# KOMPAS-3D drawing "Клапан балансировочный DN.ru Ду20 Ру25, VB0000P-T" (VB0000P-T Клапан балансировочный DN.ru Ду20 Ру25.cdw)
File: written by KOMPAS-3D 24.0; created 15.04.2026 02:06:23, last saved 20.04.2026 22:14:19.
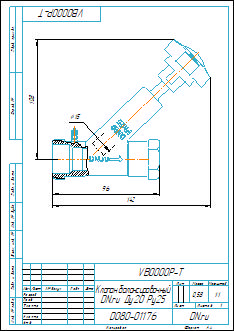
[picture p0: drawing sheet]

Document properties: Автор: DN.ru; Форматы листов документа: A4; Полное имя файла: VB0000P-T Клапан балансировочный DN.ru Ду20 Ру25.m3d; Масса: 0.58; Наименование: Клапан балансировочный DN.ru Ду20 Ру25; Количество листов документа: 1; Примечание: D080-01176

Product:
- Part/product: Клапан балансировочный DN.ru Ду20 Ру25  | designation VB0000P-T
    Масса: 0.58
    Раздел спецификации: Прочие изделия
    Примечание: D080-01176

Views: Вид 1, Местный разрез 1, Вид:1
Referenced files in C:\Работа\VB0000P-T DN X PN 25 Клапан балансировочный DN.ru\DN15\: VB0000P-T DN15 PN25 Клапан балансировочный DN.ru.m3d
Referenced files in E:\Работа\Зайцев\АУТСОРС\Диман\Балансировка\VB0000P-T Клапан балансировочный DN.ru Ду15-50 Ру25\DN20\: VB0000P-T Клапан балансировочный DN.ru Ду20 Ру25.m3d
Referenced files in C:\Program Files\ASCON\KOMPAS-3D v24\Templates\: Чертеж_DN.ru.cdt
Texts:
  VB0000P-T
  Чертеж_DN.ru.cdt
  Клапан балансировочный
  DN.ru Ду20 Ру25
  Клапан балансировочный DN.ru Ду20 Ру25
  VB0000P-T Клапан балансировочный DN.ru Ду20 Ру25
Dimensions and other numbers on the sheet: 0; 3; 2; 4; 96; 108; 142; 1:1; 1; 0,58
